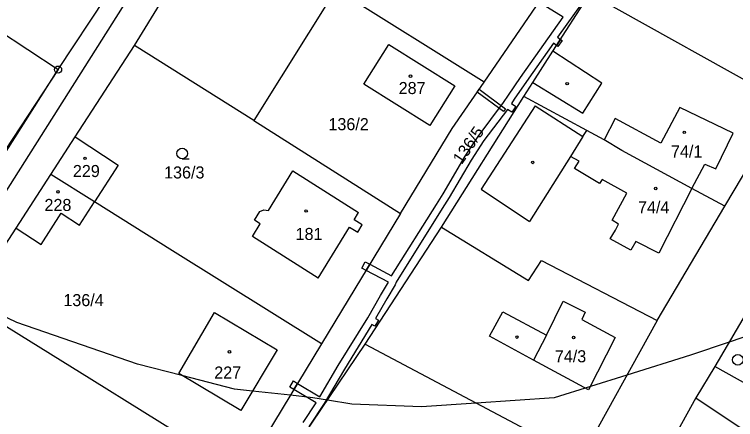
# Model space of a CAD drawing. Extents: x -747333 to -745433, y -1133152 to -1130600.
# Drawn here: x -746438.2 to -746336.6, y -1131861.6 to -1131804.5 of the extents above; entities that cross this region are included whole.
import ezdxf

# ---------------------------------------------------------------- set-up
doc = ezdxf.new("R2010")
doc.units = 0
for name, color, linetype in [('Vrstva 1', 7, 'Continuous'), ('Vrstva 18', 7, 'Continuous'), ('Vrstva 19', 7, 'Continuous'), ('Vrstva 24', 7, 'Continuous'), ('Vrstva 25', 7, 'Continuous'), ('Vrstva 3', 7, 'Continuous'), ('Vrstva 30', 7, 'Continuous'), ('Vrstva 37', 7, 'Continuous'), ('Vrstva 4', 7, 'Continuous'), ('Vrstva 52', 7, 'Continuous')]:
    doc.layers.add(name, color=color, linetype=linetype)

msp = doc.modelspace()

# ---------------------------------------------------------------- linework, layer by layer
at = {"layer": 'Vrstva 1'}
for p, q in [((-746467.98, -1131788.59), (-746432.08, -1131812.26)), ((-746432.08, -1131812.26), (-746421.07, -1131795.57)), ((-746389, -1131814.31), (-746385.5, -1131808.73)), ((-746385.5, -1131808.73), (-746376.19, -1131814.56)), ((-746432.08, -1131812.26), (-746443.09, -1131828.96)), ((-746379.7, -1131820.14), (-746389, -1131814.31)), ((-746376.19, -1131814.56), (-746379.7, -1131820.14))]:
    msp.add_line(p, q, dxfattribs=at)
for points in [[(-746421.32, -1131808.85), (-746409.98, -1131790.4)], [(-746372.05, -1131814.02), (-746359.64, -1131795.9)], [(-746392.96, -1131800.95), (-746404.51, -1131819.44)], [(-746372.05, -1131814.02), (-746392.96, -1131800.95)], [(-746362.37, -1131809.67), (-746357.15, -1131801.57)], [(-746329.51, -1131817), (-746357.15, -1131801.57)], [(-746429.68, -1131821.74), (-746421.32, -1131808.85)], [(-746404.51, -1131819.44), (-746421.32, -1131808.85)], [(-746365.19, -1131814.06), (-746362.37, -1131809.67)], [(-746376.54, -1131820.58), (-746372.05, -1131814.02)], [(-746366.45, -1131816.06), (-746365.19, -1131814.06)], [(-746378.06, -1131834.44), (-746366.45, -1131816.06)], [(-746357.6, -1131820.84), (-746366.45, -1131816.06)], [(-746338.17, -1131831.49), (-746329.51, -1131817)], [(-746404.51, -1131819.44), (-746383.82, -1131832.55)], [(-746383.82, -1131832.55), (-746376.54, -1131820.58)], [(-746355.14, -1131822.17), (-746357.6, -1131820.84)], [(-746433.1, -1131827.02), (-746429.68, -1131821.74)], [(-746429.68, -1131821.74), (-746423.64, -1131825.73), (-746426.94, -1131830.89)], [(-746352.66, -1131823.64), (-746355.14, -1131822.17)], [(-746342.8, -1131829.01), (-746352.66, -1131823.64)], [(-746402.44, -1131832.12), (-746399, -1131826.54)], [(-746399, -1131826.54), (-746389.76, -1131832.4)], [(-746438.01, -1131834.6), (-746433.1, -1131827.02)], [(-746426.94, -1131830.89), (-746433.1, -1131827.02)], [(-746338.17, -1131831.49), (-746342.8, -1131829.01)], [(-746438.01, -1131834.6), (-746434.48, -1131836.9), (-746431.65, -1131832.5), (-746429.05, -1131834.18), (-746426.94, -1131830.89)], [(-746415.96, -1131837.77), (-746426.94, -1131830.89)], [(-746403.68, -1131832.25), (-746403.09, -1131832)], [(-746403.09, -1131832), (-746402.44, -1131832.12)], [(-746347.69, -1131847.59), (-746338.17, -1131831.49)], [(-746404.4, -1131833.49), (-746403.68, -1131832.25)], [(-746383.82, -1131832.55), (-746394.96, -1131850.9)], [(-746390.38, -1131833.41), (-746389.76, -1131832.4)], [(-746404.71, -1131835.79), (-746403.6, -1131833.99)], [(-746403.6, -1131833.99), (-746404.4, -1131833.49)], [(-746389.23, -1131834.12), (-746390.38, -1131833.41)], [(-746444.83, -1131845.11), (-746438.01, -1131834.6)], [(-746395.45, -1131841.62), (-746391.02, -1131834.44)], [(-746391.02, -1131834.44), (-746389.86, -1131835.15)], [(-746389.86, -1131835.15), (-746389.23, -1131834.12)], [(-746388.82, -1131850.94), (-746378.06, -1131834.44)], [(-746378.06, -1131834.44), (-746365.8, -1131841.96)], [(-746395.45, -1131841.62), (-746404.71, -1131835.79)], [(-746394.96, -1131850.9), (-746415.96, -1131837.77)], [(-746365.8, -1131841.96), (-746363.99, -1131839.14)], [(-746363.99, -1131839.14), (-746347.69, -1131847.59)], [(-746332.13, -1131841.46), (-746339.57, -1131854.09)], [(-746427.32, -1131855.97), (-746443.47, -1131845.95)], [(-746415.09, -1131855.08), (-746410.03, -1131846.49)], [(-746410.03, -1131846.49), (-746401.23, -1131851.72)], [(-746347.69, -1131847.59), (-746358.44, -1131867.04)], [(-746394.96, -1131850.9), (-746406.07, -1131869.18)], [(-746402.47, -1131871.17), (-746388.82, -1131850.94)], [(-746388.82, -1131850.94), (-746358.44, -1131867.04)], [(-746401.23, -1131851.72), (-746406.32, -1131860.29)], [(-746339.57, -1131854.09), (-746342.22, -1131858.51)], [(-746334.77, -1131856.76), (-746339.57, -1131854.09)], [(-746406.32, -1131860.29), (-746415.09, -1131855.08)], [(-746406.07, -1131869.18), (-746427.32, -1131855.97)], [(-746342.22, -1131858.51), (-746353.37, -1131878.68)], [(-746342.22, -1131858.51), (-746319.24, -1131873.86)]]:
    msp.add_lwpolyline(points, dxfattribs=at)
at = {"layer": 'Vrstva 24'}
msp.add_line((-746432.115355, -1131812.224645), (-746432.044645, -1131812.295355), dxfattribs=at)
msp.add_circle((-746432.08, -1131812.26), 0.499289, dxfattribs=at)
at = {"layer": 'Vrstva 25'}
msp.add_line((-746414.61, -1131824.84), (-746413.61, -1131824.84), dxfattribs=at)
for centre, radius in [((-746382.43, -1131813.19), 0.174503), ((-746360.36, -1131814.25), 0.174503), ((-746343.86, -1131821.09), 0.174503), ((-746414.61, -1131824.09), 0.75), ((-746428.28, -1131824.76), 0.174503), ((-746365.21, -1131825.34), 0.174503), ((-746347.89, -1131829.01), 0.174503), ((-746432.1, -1131829.48), 0.174503), ((-746397.14, -1131832.17), 0.174503), ((-746367.43, -1131849.94), 0.174503), ((-746359.45, -1131850), 0.174503), ((-746407.94, -1131852.02), 0.174503), ((-746336.31, -1131853.15), 0.75)]:
    msp.add_circle(centre, radius, dxfattribs=at)
at = {"layer": 'Vrstva 3'}
for points in [[(-746389, -1131814.31), (-746385.5, -1131808.73)], [(-746385.5, -1131808.73), (-746376.19, -1131814.56)], [(-746379.7, -1131820.14), (-746389, -1131814.31)], [(-746376.19, -1131814.56), (-746379.7, -1131820.14)], [(-746344.47, -1131817.61), (-746347.15, -1131822.64)], [(-746336.96, -1131821.23), (-746344.47, -1131817.61)], [(-746353.59, -1131819.15), (-746355.14, -1131822.17)], [(-746347.15, -1131822.64), (-746353.59, -1131819.15)], [(-746358.14, -1131821.7), (-746357.6, -1131820.84)], [(-746355.14, -1131822.17), (-746357.6, -1131820.84)], [(-746433.1, -1131827.02), (-746429.68, -1131821.74)], [(-746429.68, -1131821.74), (-746423.64, -1131825.73), (-746426.94, -1131830.89)], [(-746358.14, -1131821.7), (-746359.91, -1131824.5)], [(-746339.44, -1131826.26), (-746336.96, -1131821.23)], [(-746352.66, -1131823.64), (-746355.14, -1131822.17)], [(-746352.66, -1131823.64), (-746355.14, -1131822.17)], [(-746342.8, -1131829.01), (-746352.66, -1131823.64)], [(-746342.8, -1131829.01), (-746352.66, -1131823.64)], [(-746358.68, -1131825.18), (-746359.91, -1131824.5)], [(-746359.31, -1131826.21), (-746358.68, -1131825.18)], [(-746342.8, -1131829.01), (-746340.98, -1131825.59)], [(-746340.98, -1131825.59), (-746339.44, -1131826.26)], [(-746402.44, -1131832.12), (-746399, -1131826.54)], [(-746399, -1131826.54), (-746389.76, -1131832.4)], [(-746355.81, -1131828.32), (-746359.31, -1131826.21)], [(-746438.01, -1131834.6), (-746433.1, -1131827.02)], [(-746426.94, -1131830.89), (-746433.1, -1131827.02)], [(-746426.94, -1131830.89), (-746433.1, -1131827.02)], [(-746355.43, -1131827.75), (-746355.81, -1131828.32)], [(-746351.94, -1131829.66), (-746355.43, -1131827.75)], [(-746354.01, -1131833.47), (-746351.94, -1131829.66)], [(-746342.8, -1131829.01), (-746347.43, -1131838.14)], [(-746438.01, -1131834.6), (-746434.48, -1131836.9), (-746431.65, -1131832.5), (-746429.05, -1131834.18), (-746426.94, -1131830.89)], [(-746403.68, -1131832.25), (-746403.09, -1131832)], [(-746403.09, -1131832), (-746402.44, -1131832.12)], [(-746404.4, -1131833.49), (-746403.68, -1131832.25)], [(-746390.38, -1131833.41), (-746389.76, -1131832.4)], [(-746404.71, -1131835.79), (-746403.6, -1131833.99)], [(-746403.6, -1131833.99), (-746404.4, -1131833.49)], [(-746389.23, -1131834.12), (-746390.38, -1131833.41)], [(-746353.11, -1131834.02), (-746354.01, -1131833.47)], [(-746353.54, -1131834.9), (-746353.11, -1131834.02)], [(-746395.45, -1131841.62), (-746391.02, -1131834.44)], [(-746391.02, -1131834.44), (-746389.86, -1131835.15)], [(-746389.86, -1131835.15), (-746389.23, -1131834.12)], [(-746354.32, -1131836.11), (-746353.54, -1131834.9)], [(-746395.45, -1131841.62), (-746404.71, -1131835.79)], [(-746351.37, -1131837.7), (-746354.32, -1131836.11)], [(-746350.68, -1131836.47), (-746351.37, -1131837.7)], [(-746347.43, -1131838.14), (-746350.68, -1131836.47)], [(-746363.27, -1131849.66), (-746360.93, -1131844.9)], [(-746360.93, -1131844.9), (-746357.84, -1131846.44)], [(-746415.09, -1131855.08), (-746410.03, -1131846.49)], [(-746410.03, -1131846.49), (-746401.23, -1131851.72)], [(-746357.84, -1131846.44), (-746358.31, -1131847.45)], [(-746358.31, -1131847.45), (-746353.62, -1131850)], [(-746363.27, -1131849.66), (-746365.09, -1131853.19)], [(-746353.62, -1131850), (-746357.37, -1131857.38)], [(-746401.23, -1131851.72), (-746406.32, -1131860.29)], [(-746357.37, -1131857.38), (-746365.09, -1131853.19)], [(-746406.32, -1131860.29), (-746415.09, -1131855.08)]]:
    msp.add_lwpolyline(points, dxfattribs=at)
at = {"layer": 'Vrstva 30'}
for p, q in [((-746400.74, -1131768.31), (-746446.4, -1131840.37)), ((-746432.08, -1131812.26), (-746421.07, -1131795.57)), ((-746448.92, -1131838.75), (-746432.08, -1131812.26)), ((-746373.03, -1131815.46), (-746372.75, -1131815.04)), ((-746369.33, -1131818.18), (-746373.03, -1131815.46)), ((-746372.75, -1131815.04), (-746369.03, -1131817.78)), ((-746369.03, -1131817.78), (-746369.33, -1131818.18))]:
    msp.add_line(p, q, dxfattribs=at)
for points in [[(-746357.15, -1131801.33), (-746361.7, -1131807.72)], [(-746360.92, -1131804.9), (-746364.34, -1131802.77)], [(-746366.92, -1131813.38), (-746360.92, -1131804.9)], [(-746362.27, -1131808.54), (-746366.1, -1131813.95)], [(-746361.85, -1131808.86), (-746362.27, -1131808.54)], [(-746361.3, -1131808.02), (-746361.85, -1131808.86)], [(-746361.85, -1131808.86), (-746361.3, -1131808.02), (-746361.07, -1131808.19), (-746361.68, -1131808.99), (-746361.85, -1131808.86)], [(-746361.7, -1131807.72), (-746361.3, -1131808.02)], [(-746368.63, -1131815.88), (-746366.92, -1131813.38)], [(-746366.1, -1131813.95), (-746367.81, -1131816.44)], [(-746369.32, -1131816.91), (-746368.63, -1131815.88)], [(-746367.81, -1131816.44), (-746368.22, -1131817.05)], [(-746372.9, -1131821.69), (-746369.32, -1131816.91)], [(-746368.22, -1131817.05), (-746367.61, -1131817.45)], [(-746367.61, -1131817.45), (-746368.16, -1131818.28)], [(-746368.79, -1131817.88), (-746372.08, -1131822.26)], [(-746368.16, -1131818.28), (-746368.79, -1131817.88)], [(-746374.72, -1131824.47), (-746372.9, -1131821.69)], [(-746372.08, -1131822.26), (-746373.88, -1131825.01)], [(-746377.83, -1131829.77), (-746374.72, -1131824.47)], [(-746373.88, -1131825.01), (-746376.97, -1131830.29)], [(-746378.79, -1131831.27), (-746377.83, -1131829.77)], [(-746376.97, -1131830.29), (-746377.95, -1131831.81)], [(-746385.09, -1131841.32), (-746378.79, -1131831.27)], [(-746377.95, -1131831.81), (-746384.45, -1131842.2)], [(-746389.3, -1131840.22), (-746388.83, -1131839.34)], [(-746388.83, -1131839.34), (-746388.16, -1131839.69)], [(-746388.68, -1131840.56), (-746388.16, -1131839.69)], [(-746388.16, -1131839.69), (-746388.68, -1131840.56)], [(-746388.16, -1131839.69), (-746385.09, -1131841.32)], [(-746388.68, -1131840.56), (-746389.3, -1131840.22)], [(-746385.54, -1131842.22), (-746388.68, -1131840.56)], [(-746386.65, -1131844.06), (-746385.54, -1131842.22)], [(-746384.57, -1131842.56), (-746385.79, -1131844.56)], [(-746384.45, -1131842.2), (-746384.57, -1131842.56)], [(-746388.45, -1131847.23), (-746386.65, -1131844.06)], [(-746385.79, -1131844.56), (-746387.35, -1131847.31)], [(-746392.6, -1131853.94), (-746388.45, -1131847.23)], [(-746387.86, -1131848.17), (-746391.74, -1131854.44)], [(-746387.46, -1131848.42), (-746387.86, -1131848.17)], [(-746386.93, -1131847.57), (-746387.46, -1131848.42)], [(-746387.35, -1131847.31), (-746386.93, -1131847.57)], [(-746395.2, -1131858.35), (-746392.6, -1131853.94)], [(-746391.74, -1131854.44), (-746394.59, -1131859.3)], [(-746399.42, -1131856.97), (-746398.91, -1131856.11)], [(-746398.91, -1131856.11), (-746398.34, -1131856.46)], [(-746398.86, -1131857.31), (-746399.42, -1131856.97)], [(-746398.86, -1131857.31), (-746398.34, -1131856.46)], [(-746398.34, -1131856.46), (-746398.86, -1131857.31)], [(-746395.73, -1131859.2), (-746398.86, -1131857.31)], [(-746398.34, -1131856.46), (-746395.2, -1131858.35)], [(-746397.55, -1131861.96), (-746395.73, -1131859.2)], [(-746394.59, -1131859.3), (-746396.71, -1131862.5)]]:
    msp.add_lwpolyline(points, dxfattribs=at)
at = {"layer": 'Vrstva 37'}
for centre in [(-746382.43, -1131813.19), (-746343.86, -1131821.09), (-746428.28, -1131824.76), (-746347.89, -1131829.01), (-746432.1, -1131829.48), (-746397.14, -1131832.17), (-746359.45, -1131850), (-746407.94, -1131852.02)]:
    msp.add_circle(centre, 0.174503, dxfattribs=at)
at = {"layer": 'Vrstva 4'}
for p, q in [((-746358.14, -1131821.7), (-746357.6, -1131820.84)), ((-746358.68, -1131825.18), (-746359.91, -1131824.5)), ((-746359.31, -1131826.21), (-746358.68, -1131825.18)), ((-746355.81, -1131828.32), (-746359.31, -1131826.21)), ((-746355.43, -1131827.75), (-746355.81, -1131828.32)), ((-746351.94, -1131829.66), (-746355.43, -1131827.75)), ((-746354.01, -1131833.47), (-746351.94, -1131829.66)), ((-746342.8, -1131829.01), (-746347.43, -1131838.14)), ((-746353.11, -1131834.02), (-746354.01, -1131833.47)), ((-746353.54, -1131834.9), (-746353.11, -1131834.02)), ((-746354.32, -1131836.11), (-746353.54, -1131834.9)), ((-746351.37, -1131837.7), (-746354.32, -1131836.11)), ((-746350.68, -1131836.47), (-746351.37, -1131837.7)), ((-746347.43, -1131838.14), (-746350.68, -1131836.47))]:
    msp.add_line(p, q, dxfattribs=at)
for points in [[(-746355.46, -1131814.18), (-746362.37, -1131809.67)], [(-746365.19, -1131814.06), (-746358.15, -1131818.41)], [(-746358.15, -1131818.41), (-746355.46, -1131814.18)], [(-746364.87, -1131817.35), (-746372.49, -1131829.12)], [(-746364.87, -1131817.35), (-746358.14, -1131821.7)], [(-746344.47, -1131817.61), (-746347.15, -1131822.64)], [(-746336.96, -1131821.23), (-746344.47, -1131817.61)], [(-746353.59, -1131819.15), (-746355.14, -1131822.17)], [(-746347.15, -1131822.64), (-746353.59, -1131819.15)], [(-746358.14, -1131821.7), (-746359.91, -1131824.5)], [(-746339.44, -1131826.26), (-746336.96, -1131821.23)], [(-746359.91, -1131824.5), (-746365.69, -1131833.66)], [(-746342.8, -1131829.01), (-746340.98, -1131825.59)], [(-746340.98, -1131825.59), (-746339.44, -1131826.26)], [(-746372.49, -1131829.12), (-746365.69, -1131833.66)], [(-746363.27, -1131849.66), (-746360.93, -1131844.9)], [(-746360.93, -1131844.9), (-746357.84, -1131846.44)], [(-746371.32, -1131849.8), (-746369.44, -1131846.38)], [(-746369.44, -1131846.38), (-746363.27, -1131849.66)], [(-746357.84, -1131846.44), (-746358.31, -1131847.45)], [(-746358.31, -1131847.45), (-746353.62, -1131850)], [(-746365.09, -1131853.19), (-746371.32, -1131849.8)], [(-746363.27, -1131849.66), (-746365.09, -1131853.19)], [(-746353.62, -1131850), (-746357.37, -1131857.38)], [(-746357.37, -1131857.38), (-746365.09, -1131853.19)]]:
    msp.add_lwpolyline(points, dxfattribs=at)
at = {"layer": 'Vrstva 52'}
msp.add_lwpolyline([(-746334.13, -1131849.5), (-746337.55, -1131850.66), (-746343, -1131852.5), (-746351.95, -1131855.3), (-746362.19, -1131858.5), (-746373.17, -1131859.23), (-746380.87, -1131859.75), (-746390.69, -1131859.38), (-746394.14, -1131858.83), (-746396.19, -1131858.5), (-746399.36, -1131858.14), (-746404.69, -1131857.54), (-746407.25, -1131857.25), (-746414.63, -1131855.35), (-746420.88, -1131853.75), (-746437.87, -1131847.88), (-746444.56, -1131844.7), (-746451.34, -1131841.47), (-746464.69, -1131835.13), (-746489.13, -1131820.66), (-746496.89, -1131816.07), (-746499.26, -1131814.66), (-746527.9, -1131797.71)], dxfattribs=at)

# ---------------------------------------------------------------- texts
at = {"layer": 'Vrstva 18'}
for s, p in [('136/2', (-746394, -1131820.8)), ('136/3', (-746417.15, -1131827.6)), ('136/4', (-746431.34, -1131845.58))]:
    msp.add_text(s, height=1.7, dxfattribs=at).set_placement(p)
msp.add_text('136/5', height=1.7, rotation=55.53918, dxfattribs=at).set_placement((-746375.21, -1131825.72))
at = {"layer": 'Vrstva 19'}
for s, p in [('287', (-746384.101545, -1131815.71)), ('74/1', (-746345.74, -1131824.65)), ('229', (-746429.997496, -1131827.4)), ('228', (-746434.001545, -1131832.18)), ('74/4', (-746350.38, -1131832.5)), ('181', (-746398.62, -1131836.26)), ('74/3', (-746362.1, -1131853.49)), ('227', (-746410.08, -1131855.78))]:
    msp.add_text(s, height=1.7, dxfattribs=at).set_placement(p)

doc.saveas('drawing.dxf')
